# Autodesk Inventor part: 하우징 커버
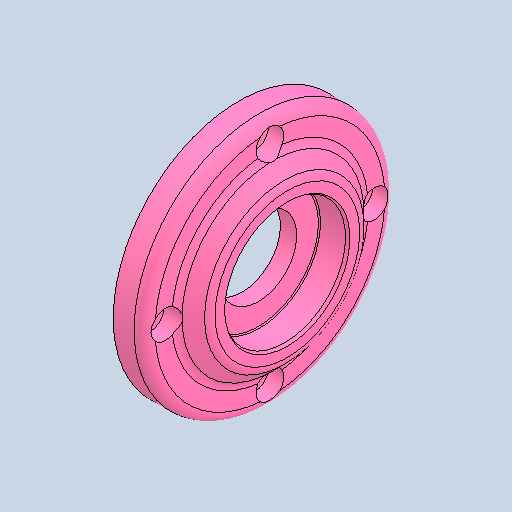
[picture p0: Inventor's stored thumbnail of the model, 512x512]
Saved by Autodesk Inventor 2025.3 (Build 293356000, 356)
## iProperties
Created: 2026-01
Part Number: 하우징 커버
Material: 알루미늄 6061
Document SubType Name: Modeling
Designer: pc6
Density: 2.7 g/cm^3
Appearance: 기본값
Author: jhkim
Sending System: Autodesk Inventor 2026
Preprocessor: ST-DEVELOPER v20.1
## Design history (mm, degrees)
feature "솔리드1"
node "솔리드2"
